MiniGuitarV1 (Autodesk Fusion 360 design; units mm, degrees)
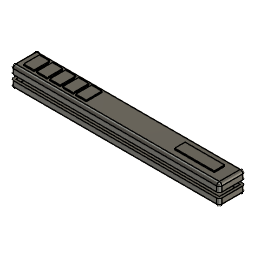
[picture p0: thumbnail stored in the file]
part number: 2026-03-23-14-49-40-062
part number: 2026-03-24-15-20-43-874
part number: 2026-03-24-15-20-43-882
sketch "Sketch1" plane through (0, 0, 0) normal (0, 0, 1) x axis (1, 0, 0)
sketch "Sketch2" plane through (0, 0, 0) normal (0, 0, 1) x axis (1, 0, 0)
sketch "Sketch3" plane through (0, 0, 0) normal (0, 0, 1) x axis (1, 0, 0)
  line L1 (200, 0) -> (-200, 0)
  line L2 (200, 50) -> (200, 0)
  line L3 (-200, 50) -> (200, 50)
  line L4 (-200, 0) -> (-200, 50)
  horizontal L1
  perpendicular L1 L2
  perpendicular L2 L3
  perpendicular L1 L4
extrude "Extrude1" new body sketch "Sketch3" along normal blind 30
sketch "Sketch4" plane through (0, 0, 0) normal (0, -1, 0) x axis (1, 0, 0)
  line L1 (200, 0) -> (-200, 0)
  line L2 (200, 30) -> (200, 0)
  line L3 (-200, 30) -> (200, 30)
  line L4 (-200, 0) -> (-200, 30)
  line L5 (50, 15) -> (-50, 15)
  horizontal L5
split "Split1"
move "Move1"
shell "Shell1" innerThickness 5
shell "Shell2" innerThickness 5
move "Move2"
fillet "Fillet1" radius 5
sketch "Sketch5" plane through (0, 0, 30) normal (0, 0, 1) x axis (-1, 0, 0)
  line L1 (-195, -45) -> (-195, -5)
  line L2 (195, -45) -> (-195, -45)
  line L3 (195, -5) -> (195, -45)
  line L4 (-195, -5) -> (195, -5)
  line L5 (-175.2089, -15) -> (-175.2089, -35)
  line L6 (-99.4485, -15) -> (-175.2089, -15)
  line L7 (-99.4485, -35) -> (-99.4485, -15)
  line L8 (-175.2089, -35) -> (-99.4485, -35)
  perpendicular L2 L5
  perpendicular L5 L6
  perpendicular L6 L7
  perpendicular L5 L8
extrude "Extrude2" add sketch "Sketch5" profile of L5 L6 L7 L8 along normal blind 2.5
sketch "Sketch6" plane through (0, 0, 30) normal (0, 0, 1) x axis (-1, 0, 0)
  line L1 (-175.2089, -35) -> (-99.4485, -35)
  line L2 (-175.2089, -15) -> (-175.2089, -35)
  line L3 (-99.4485, -15) -> (-175.2089, -15)
  line L4 (-99.4485, -35) -> (-99.4485, -15)
  line L5 (-195, -45) -> (-195, -5)
  line L6 (195, -45) -> (-195, -45)
  line L7 (195, -5) -> (195, -45)
  line L8 (-195, -5) -> (195, -5)
  line L9 (185, -10.0285) -> (185, -35)
  line L10 (165, -10.0285) -> (185, -10.0285)
  line L11 (165, -40) -> (165, -10.0285)
  line L12 (185, -40) -> (165, -40)
  line L13 (185, -35) -> (185, -40)
  perpendicular L6 L9
  perpendicular L9 L10
  perpendicular L10 L11
  perpendicular L11 L12
  perpendicular L12 L13
extrude "Extrude3" add sketch "Sketch6" profile of L9 L10 L11 L12 L13 along normal blind 2.5
sketch "Sketch7" plane through (0, 0, 30) normal (0, 0, 1) x axis (-1, 0, 0)
  line L1 (165, -40) -> (185, -40)
  line L2 (165, -10.0285) -> (165, -40)
  line L3 (185, -10.0285) -> (165, -10.0285)
  line L4 (185, -40) -> (185, -10.0285)
  line L5 (-175.2089, -35) -> (-99.4485, -35)
  line L6 (-175.2089, -15) -> (-175.2089, -35)
  line L7 (-99.4485, -15) -> (-175.2089, -15)
  line L8 (-99.4485, -35) -> (-99.4485, -15)
  line L9 (-195, -45) -> (-195, -5)
  line L10 (195, -45) -> (-195, -45)
  line L11 (195, -5) -> (195, -45)
  line L12 (-195, -5) -> (195, -5)
  line L13 (140, -40) -> (160, -40)
  line L14 (140, -10) -> (140, -40)
  line L15 (160, -10) -> (140, -10)
  line L16 (160, -40) -> (160, -10)
  parallel L10 L13
  perpendicular L13 L14
  perpendicular L14 L15
  perpendicular L13 L16
sketch "Sketch8" plane through (0, 0, 30) normal (0, 0, 1) x axis (-1, 0, 0)
  line L1 (115, -40) -> (135, -40)
  line L2 (115, -10) -> (115, -40)
  line L3 (135, -10) -> (115, -10)
  line L4 (135, -40) -> (135, -10)
  line L5 (90, -40) -> (110, -40)
  line L6 (90, -10) -> (90, -40)
  line L7 (110, -10) -> (90, -10)
  line L8 (110, -40) -> (110, -10)
  line L9 (65, -40) -> (85, -40)
  line L10 (65, -10) -> (65, -40)
  line L11 (85, -10) -> (65, -10)
  line L12 (85, -40) -> (85, -10)
  horizontal L1
  perpendicular L1 L2
  perpendicular L2 L3
  perpendicular L1 L4
  perpendicular L2 L5
  perpendicular L1 L6
  perpendicular L6 L7
  perpendicular L7 L8
  perpendicular L6 L9
  perpendicular L5 L10
  perpendicular L6 L11
  perpendicular L9 L12
extrude "Extrude4" add sketch "Sketch7" profile of L13 L14 L15 L16 along normal blind 2.5
extrude "Extrude5" add sketch "Sketch8" profile of L1 L2 L3 L4 along normal blind 2.5
sketch "Sketch9" plane through (0, 0, 30) normal (0, 0, 1) x axis (-1, 0, 0)
  line L1 (135, -40) -> (135, -10)
  line L2 (115, -40) -> (135, -40)
  line L3 (115, -10) -> (115, -40)
  line L4 (135, -10) -> (115, -10)
  line L5 (160, -40) -> (160, -10)
  line L6 (140, -40) -> (160, -40)
  line L7 (140, -10) -> (140, -40)
  line L8 (160, -10) -> (140, -10)
  line L9 (165, -40) -> (185, -40)
  line L10 (165, -10.0285) -> (165, -40)
  line L11 (185, -10.0285) -> (165, -10.0285)
  line L12 (185, -40) -> (185, -10.0285)
  line L13 (-175.2089, -35) -> (-99.4485, -35)
  line L14 (-175.2089, -15) -> (-175.2089, -35)
  line L15 (-99.4485, -15) -> (-175.2089, -15)
  line L16 (-99.4485, -35) -> (-99.4485, -15)
  line L17 (-195, -45) -> (-195, -5)
  line L18 (195, -45) -> (-195, -45)
  line L19 (195, -5) -> (195, -45)
  line L20 (-195, -5) -> (195, -5)
  line L21 (90, -40) -> (110, -40)
  line L22 (90, -10) -> (90, -40)
  line L23 (110, -10) -> (90, -10)
  line L24 (110, -40) -> (110, -10)
  line L25 (65, -40) -> (85, -40)
  line L26 (65, -10) -> (65, -40)
  line L27 (85, -10) -> (65, -10)
  line L28 (85, -40) -> (85, -10)
  perpendicular L3 L21
  perpendicular L21 L22
  perpendicular L3 L23
  perpendicular L4 L24
  perpendicular L24 L25
  perpendicular L25 L26
  perpendicular L26 L27
  perpendicular L25 L28
extrude "Extrude6" add sketch "Sketch9" profile of L21 L22 L23 L24 along normal blind 2.5
sketch "Sketch10" plane through (0, 0, 30) normal (0, 0, 1) x axis (-1, 0, 0)
  line L1 (110, -40) -> (110, -10)
  line L2 (90, -40) -> (110, -40)
  line L3 (90, -10) -> (90, -40)
  line L4 (110, -10) -> (90, -10)
  line L5 (135, -40) -> (135, -10)
  line L6 (115, -40) -> (135, -40)
  line L7 (115, -10) -> (115, -40)
  line L8 (135, -10) -> (115, -10)
  line L9 (160, -40) -> (160, -10)
  line L10 (140, -40) -> (160, -40)
  line L11 (140, -10) -> (140, -40)
  line L12 (160, -10) -> (140, -10)
  line L13 (165, -40) -> (185, -40)
  line L14 (165, -10.0285) -> (165, -40)
  line L15 (185, -10.0285) -> (165, -10.0285)
  line L16 (185, -40) -> (185, -10.0285)
  line L17 (-175.2089, -35) -> (-99.4485, -35)
  line L18 (-175.2089, -15) -> (-175.2089, -35)
  line L19 (-99.4485, -15) -> (-175.2089, -15)
  line L20 (-99.4485, -35) -> (-99.4485, -15)
  line L21 (-195, -45) -> (-195, -5)
  line L22 (195, -45) -> (-195, -45)
  line L23 (195, -5) -> (195, -45)
  line L24 (-195, -5) -> (195, -5)
  line L25 (65, -40) -> (85, -40)
  line L26 (65, -10) -> (65, -40)
  line L27 (85, -10) -> (65, -10)
  line L28 (85, -40) -> (85, -10)
  perpendicular L3 L25
  perpendicular L2 L26
  perpendicular L26 L27
  perpendicular L25 L28
extrude "Extrude7" add sketch "Sketch10" profile of L25 L26 L27 L28 along normal blind 2.5
move "Move3"
component_from_bodies "Body->Comp1"
component_from_bodies "Body->Comp2"
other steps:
base_feature "Base Feature1"
base_feature "Base Feature1"
create_component "CreateComponent1"
reparent_decal "ReparentDecal1"
remove_body "RemoveBody1"
create_component "CreateComponent2"
reparent_decal "ReparentDecal2"
remove_body "RemoveBody2"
